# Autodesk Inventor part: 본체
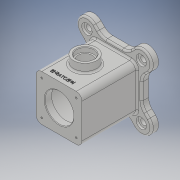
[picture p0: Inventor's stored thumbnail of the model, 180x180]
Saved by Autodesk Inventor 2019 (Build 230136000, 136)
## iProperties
Created: 2021-01
Part Number: 본체
Material: 일반
Document SubType Name: Modeling
Designer: 3dpro6
Density: 1 g/cm^3
Appearance: 기본값
Mass: 385.772 g
Surface Area: 854.467 cm^2
Volume: 385.772 cm^3
Author: 3dpro6
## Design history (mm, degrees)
sketch "스케치1"
  geometry: L1 (22.544, 48)-(-22.544, 48); L2 (-48, 22.544)-(-48, -22.544); L3 (-22.544, -48)-(22.544, -48); L4 (48, -22.544)-(48, 22.544); L5 (47.376, -47.376)-(0, 0); L6 (0, 0)-(-47.376, -47.376); L7 (47.376, 47.376)-(0, 0); L8 (-47.376, 47.376)-(0, 0); L9 (-34.648, -60.104)-(-22.544, -48); L10 (-60.104, -34.648)-(-48, -22.544); L11 (34.648, -60.104)-(22.544, -48); L12 (60.104, -34.648)-(48, -22.544); L13 (60.104, 34.648)-(48, 22.544); L14 (34.648, 60.104)-(22.544, 48); L15 (-34.648, 60.104)-(-22.544, 48); L16 (-60.104, 34.648)-(-48, 22.544); C1 r 25 at (0, 0); A1 r 18 centre (47.376, -47.376) between (34.648, -60.104) and (60.104, -34.648); A2 r 18 centre (-47.376, -47.376) between (-60.104, -34.648) and (-34.648, -60.104); A3 r 18 centre (47.376, 47.376) between (60.104, 34.648) and (34.648, 60.104); A4 r 18 centre (-47.376, 47.376) between (-34.648, 60.104) and (-60.104, 34.648); A5 r 67 centre (0, 0) between (47.376, -47.376) and (-47.376, -47.376); 9 further points
  constraints: 32 end point, 20 point on circle, 10 parallel, 9 point on line, 8 tangent, 6 centre point, 2 coincident, 2 perpendicular, 1 horizontal, 1 horizontal alignment, 1 vertical alignment
  dimensions: "d2" = 36 diameter of A1; "d3" = 36 diameter of A2; "d4" = 36 diameter of A3; "d5" = 36 diameter of A4; "d7" = 134 diameter of A5; "d8" = 96 distance between parallel lines of L1 L3; "d9" = 96 distance between parallel lines of L2 L4; "d10" = 48 distance from line of L4 point (0, 0); "d11" = 48 distance from line of L3 point (0, 0); "d12" = 50 diameter of C1; "d56" = 90 deg angle of L6 L5; "d57" = 90 deg angle of L8 L6
extrude "돌출1" new body sketch "스케치1" distance "d13" = 12; taper "d14" = 0 deg
sketch "스케치2"
  geometry: L1 (-40, -40)-(40, -40); L2 (40, -40)-(40, 40); L3 (40, 40)-(-40, 40); L4 (-40, 40)-(-40, -40); L5 (-40, -40)-(40, 40); L6 (40, -40)-(-40, 40); 1 further point
  constraints: 12 end point, 2 midpoint, 2 parallel, 1 horizontal, 1 perpendicular
  dimensions: "d15" = 80 distance of L3.end L2.end; "d16" = 80 distance of L2.end L1.end
extrude "돌출2" join sketch "스케치2" distance "d17" = 96; taper "d18" = 0 deg
sketch "스케치3"
  geometry: L1 (22.544, -48)-(-22.544, -48) reference; L2 (48, 22.544)-(48, -22.544) reference; L3 (-22.544, 48)-(22.544, 48) reference; L4 (-48, -22.544)-(-48, 22.544) reference; L5 (-30, -30)-(30, -30); L6 (30, -30)-(30, 30); L7 (30, 30)-(-30, 30); L8 (-30, 30)-(-30, -30); L9 (-30, -30)-(30, 30); L10 (30, -30)-(-30, 30); L11 (-60.104, -34.648)-(-48, -22.544) reference; L12 (-22.544, -48)-(-34.648, -60.104) reference; L13 (34.648, -60.104)-(22.544, -48) reference; L14 (48, -22.544)-(60.104, -34.648) reference; L15 (60.104, 34.648)-(48, 22.544) reference; L16 (22.544, 48)-(34.648, 60.104) reference; L17 (-34.648, 60.104)-(-22.544, 48) reference; L18 (-48, 22.544)-(-60.104, 34.648) reference; C1 r 25 at (0, 0) reference; A1 r 18 centre (-47.376, -47.376) between (-60.104, -34.648) and (-34.648, -60.104) reference; A2 r 18 centre (47.376, -47.376) between (34.648, -60.104) and (60.104, -34.648) reference; A3 r 18 centre (47.376, 47.376) between (60.104, 34.648) and (34.648, 60.104) reference; A4 r 18 centre (-47.376, 47.376) between (-34.648, 60.104) and (-60.104, 34.648) reference; 4 further points
  constraints: 12 end point, 3 coincident, 2 midpoint, 2 parallel, 1 horizontal, 1 perpendicular
  dimensions: "d19" = 60 distance of L7.end L6.end; "d20" = 60 distance of L6.end L5.end
hole "구멍1" sketch "스케치3" at (30, -30), (-30, 30), (-30, -30), (30, 30) diameter "d21" = 3.242; stored, may be unused: countersink angle "d25" = 90 deg, drill point angle "d27" = 118 deg; dims "d22" = 8, "d23" = 4, "d24" = 2, "d26" = 10
sketch "스케치4"
  geometry: L1 (-30, 30)-(30, 30); L2 (30, 30)-(30, -30); L3 (30, -30)-(-30, -30); L4 (-30, -30)-(-30, 30); L5 (-30, 30)-(30, -30); L6 (30, 30)-(-30, -30); C1 r 1.621 at (-30, 30) reference; 5 further points
  constraints: 12 end point, 4 coincident, 2 midpoint, 2 parallel, 1 horizontal, 1 perpendicular
  dimensions: "d28" = 60 distance of L2.end L3.end; "d29" = 60 distance of L1.end L2.end
hole "구멍2" sketch "스케치4" at (30, 30), (30, -30), (-30, -30), (-30, 30) diameter "d30" = 3.242; stored, may be unused: countersink angle "d34" = 90 deg, drill point angle "d36" = 118 deg; dims "d31" = 8, "d32" = 4, "d33" = 2, "d35" = 10
sketch "스케치5"
  geometry: C1 r 25 at (0, 0); 1 further point
  constraints: 1 centre point, 1 coincident
  dimensions: "d37" = 50 diameter of C1
extrude "돌출3" cut sketch "스케치5" distance "d38" = 96; taper "d39" = 0 deg
sketch "스케치6"
  geometry: L1 (0, 133.167)-(0, -26.833); L2 (0, 12)-(35, 12); L3 (0, 96)-(35, 96); L4 (25, 0)-(-25, 0) reference; L5 (-25, 108)-(25, 108) reference; L6 (25, 0)-(25, 108) reference; L7 (35, 96)-(35, 12); L8 (0, 96)-(0, 12); 1 further point
  constraints: 10 end point, 3 point on line, 2 horizontal, 1 collinear, 1 vertical
  dimensions: "d40" = 160 distance of L1.start L1.end; "d41" = 35 distance of L2.start L2.end; "d42" = 35 distance of L3.start L3.end; "d43" = 12 distance between parallel lines of L2 L4; "d44" = 12 distance between parallel lines of L3 L5
revolve "회전1" sketch "스케치6" stored, may be unused: angle "d45" = 90 deg
sketch "스케치7"
  geometry: A1 r 18 centre (47.376, -47.376) between (34.648, -60.104) and (60.104, -34.648) reference; 4 further points
  constraints: 1 coincident
hole "구멍3" sketch "스케치7" at (47.376, -47.376) diameter "d46" = 10; stored, may be unused: countersink angle "d50" = 90 deg, drill point angle "d52" = 0 deg; dims "d47" = 8, "d48" = 18, "d49" = 4, "d51" = 10
sketch "스케치8"
  geometry: L1 (17.456, -12)-(62.544, -12) reference; C1 r 20 at (43.542, 47); 3 further points
  constraints: 1 centre point, 1 point on line, 1 vertical alignment
  dimensions: "d58" = 40 diameter of C1; "d59" = 59 distance from line of L1 C1.centre
extrude "돌출4" join sketch "스케치8" distance "d60" = 15; taper "d61" = 0 deg
sketch "스케치9"
  geometry: C1 r 20 at (0, 0) reference; 2 further points
  constraints: 1 coincident
hole "구멍4" sketch "스케치9" at (0, 0) diameter "d62" = 25; stored, may be unused: countersink angle "d66" = 90 deg, drill point angle "d68" = 0 deg; dims "d63" = 6, "d64" = 30, "d65" = 8, "d67" = 25
sketch "스케치10"
  geometry: L1 (0, 96)-(80, 96) reference; L2 (17.456, -12)-(62.544, -12) reference; 4 further points
  constraints: 1 point on line, 1 vertical alignment, 1 other
  dimensions: "d69" = 10 distance from line of L1 point (43.542, 86)
feature "엠보싱1" sketch "스케치10" dims "d4" = 36, "d17" = 96, "d70" = 0.5, "d71" = 0
fillet "모깎기1" dims "d72" = 10
fillet "모깎기3" dims "d74" = 20
fillet "모깎기4" dims "d75" = 3
chamfer "모따기1" distance "d76" = 1; stored, may be unused: second distance "d77" = 2, angle "d78" = 45 deg
fillet "모깎기5" dims "d79" = 3
node "솔리드1"
pattern_circular "원형 패턴1" dims angle "d54" = 360 deg
node "투영된 루프1"
